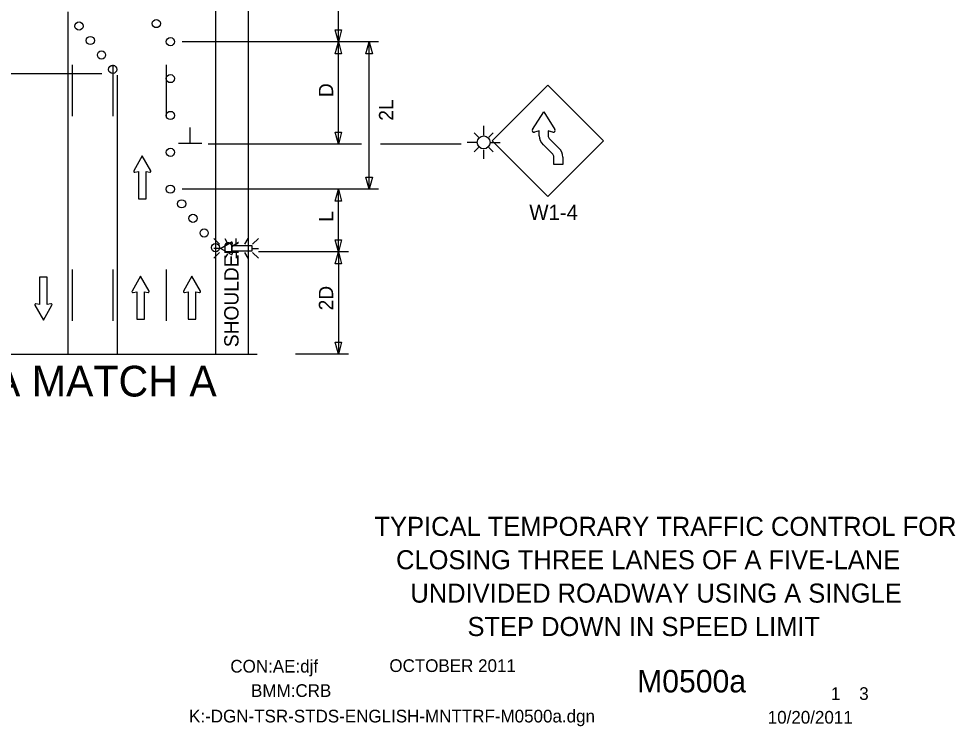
# Model space of a CAD drawing. Extents: x 16738 to 19504, y 5697 to 6916.
# Drawn here: x 16987.4 to 17444.4, y 5931.8 to 6277.3 of the extents above; entities that cross this region are included whole.
import ezdxf

# ---------------------------------------------------------------- set-up
doc = ezdxf.new("R2010")
doc.units = 0
for name, color, linetype in [('ALI_LEGAL_EX', 7, 'Continuous'), ('BORDER', 7, 'Continuous'), ('BORDER_SIGNAL_WO', 7, 'Continuous'), ('MT_SCRATCH_LEVEL_E', 7, 'Continuous'), ('PAVT_EDGE_EX', 7, 'Continuous'), ('TRAFFIC_SIGNS_PR', 7, 'Continuous'), ('TYPICAL_TEXT_DIMEN_PR', 7, 'Continuous')]:
    doc.layers.add(name, color=color, linetype=linetype)

msp = doc.modelspace()

# ---------------------------------------------------------------- linework, layer by layer
at = {"layer": 'ALI_LEGAL_EX'}
for points in [[(17013.43, 6254.77), (17013.43, 6229.77)], [(17033.43, 6254.77), (17033.43, 6229.77)], [(17059.43, 6254.77), (17059.43, 6229.77)], [(17013.43, 6154.77), (17013.43, 6129.77)], [(17033.43, 6154.77), (17033.43, 6129.77)], [(17059.43, 6154.77), (17059.43, 6129.77)]]:
    msp.add_lwpolyline(points, dxfattribs=at)
at = {"layer": 'MT_SCRATCH_LEVEL_E'}
for p, q in [((17047.71, 6210.28), (17043.6, 6203.04)), ((17047.71, 6210.28), (17043.6, 6203.04)), ((17051.85, 6203.04), (17047.71, 6210.28)), ((17051.85, 6203.04), (17047.71, 6210.28)), ((17044.08, 6202.35), (17045.85, 6202.67)), ((17044.08, 6202.35), (17045.85, 6202.67)), ((17045.85, 6202.67), (17045.85, 6189.41)), ((17045.85, 6202.67), (17045.85, 6189.41)), ((17049.6, 6189.41), (17049.6, 6202.67)), ((17049.6, 6202.67), (17051.37, 6202.35)), ((17049.6, 6189.41), (17049.6, 6202.67)), ((17049.6, 6202.67), (17051.37, 6202.35)), ((17045.85, 6189.41), (17049.6, 6189.41)), ((17045.85, 6189.41), (17049.6, 6189.41)), ((17046.87, 6151.51), (17042.76, 6144.27)), ((17046.87, 6151.51), (17042.76, 6144.27)), ((17051.02, 6144.27), (17046.87, 6151.51)), ((17051.02, 6144.27), (17046.87, 6151.51)), ((17071.96, 6151.51), (17067.85, 6144.27)), ((17071.96, 6151.51), (17067.85, 6144.27)), ((17076.11, 6144.27), (17071.96, 6151.51)), ((17076.11, 6144.27), (17071.96, 6151.51)), ((17001.36, 6151.05), (16997.62, 6151.05)), ((16997.62, 6151.05), (16997.62, 6137.79)), ((17001.36, 6151.05), (16997.62, 6151.05)), ((16997.62, 6151.05), (16997.62, 6137.79)), ((17001.36, 6137.79), (17001.36, 6151.05)), ((17001.36, 6137.79), (17001.36, 6151.05)), ((17043.24, 6143.59), (17045.02, 6143.9)), ((17043.24, 6143.59), (17045.02, 6143.9)), ((17045.02, 6143.9), (17045.02, 6130.64)), ((17045.02, 6143.9), (17045.02, 6130.64)), ((17048.76, 6130.64), (17048.76, 6143.9)), ((17048.76, 6143.9), (17050.54, 6143.59)), ((17048.76, 6130.64), (17048.76, 6143.9)), ((17048.76, 6143.9), (17050.54, 6143.59)), ((17068.33, 6143.59), (17070.11, 6143.9)), ((17068.33, 6143.59), (17070.11, 6143.9)), ((17070.11, 6143.9), (17070.11, 6130.64)), ((17070.11, 6143.9), (17070.11, 6130.64)), ((17073.85, 6130.64), (17073.85, 6143.9)), ((17073.85, 6143.9), (17075.63, 6143.59)), ((17073.85, 6130.64), (17073.85, 6143.9)), ((17073.85, 6143.9), (17075.63, 6143.59)), ((16997.62, 6137.79), (16995.84, 6138.11)), ((16997.62, 6137.79), (16995.84, 6138.11)), ((17003.14, 6138.11), (17001.36, 6137.79)), ((17003.14, 6138.11), (17001.36, 6137.79)), ((16995.36, 6137.42), (16999.51, 6130.18)), ((16995.36, 6137.42), (16999.51, 6130.18)), ((16999.51, 6130.18), (17003.62, 6137.42)), ((16999.51, 6130.18), (17003.62, 6137.42)), ((17045.02, 6130.64), (17048.76, 6130.64)), ((17045.02, 6130.64), (17048.76, 6130.64)), ((17070.11, 6130.64), (17073.85, 6130.64)), ((17070.11, 6130.64), (17073.85, 6130.64))]:
    msp.add_line(p, q, dxfattribs=at)
for centre, start, end in [((17044, 6202.81), 150.4248, 279.9638), ((17044, 6202.81), 150.4248, 279.9638), ((17051.44, 6202.81), 260.0362, 29.7731), ((17051.44, 6202.81), 260.0362, 29.7731), ((17043.17, 6144.04), 150.4248, 279.9638), ((17043.17, 6144.04), 150.4248, 279.9638), ((17050.61, 6144.05), 260.0362, 29.7731), ((17050.61, 6144.05), 260.0362, 29.7731), ((17068.26, 6144.04), 150.4248, 279.9638), ((17068.26, 6144.04), 150.4248, 279.9638), ((17075.7, 6144.05), 260.0362, 29.7731), ((17075.7, 6144.05), 260.0362, 29.7731), ((16995.77, 6137.65), 80.0362, 209.7731), ((16995.77, 6137.65), 80.0362, 209.7731), ((17003.21, 6137.65), 330.4248, 99.9638), ((17003.21, 6137.65), 330.4248, 99.9638)]:
    msp.add_arc(centre, 0.463, start, end, dxfattribs=at)
at = {"layer": 'PAVT_EDGE_EX'}
for p, q in [((17083.43, 6911.29), (17083.43, 6113.54)), ((17099.43, 6911.29), (17099.43, 6113.54)), ((17011.43, 6280.66), (17011.43, 6113.54)), ((17035.43, 6249.79), (17035.43, 6113.54))]:
    msp.add_line(p, q, dxfattribs=at)
at = {"layer": 'TRAFFIC_SIGNS_PR'}
for p, q in [((17218.42, 6217.62), (17245.57, 6244.77)), ((17272.73, 6217.62), (17245.57, 6244.77)), ((17214.33, 6220.44), (17214.33, 6224.94)), ((17211.81, 6219.39), (17209.71, 6221.5)), ((17216.84, 6219.39), (17218.95, 6221.5)), ((17211.17, 6216.88), (17206.34, 6216.88)), ((17217.48, 6216.88), (17222.36, 6216.88)), ((17245.57, 6190.47), (17218.42, 6217.62)), ((17247.99, 6211.1), (17243.28, 6215.82)), ((17247.99, 6211.1), (17243.28, 6215.82)), ((17272.73, 6217.62), (17245.57, 6190.47)), ((17251.04, 6214.15), (17246.33, 6218.87)), ((17246.33, 6218.87), (17251.04, 6214.15)), ((17211.81, 6214.37), (17209.71, 6212.26)), ((17214.33, 6208.91), (17214.33, 6213.33)), ((17216.84, 6214.37), (17218.95, 6212.26)), ((17082.56, 6170.02), (17085.38, 6167.2)), ((17088, 6170.02), (17089.21, 6167.93)), ((17093.47, 6167.2), (17093.47, 6170.02)), ((17099.26, 6170.02), (17097.63, 6167.2)), ((17101.55, 6167.2), (17104.38, 6170.02)), ((17085.38, 6165.17), (17082.56, 6165.17)), ((17101.55, 6165.17), (17104.38, 6165.17)), ((17082.56, 6160.32), (17085.38, 6163.14)), ((17089.29, 6162.5), (17088.03, 6160.32)), ((17093.47, 6163.14), (17093.47, 6160.32)), ((17097.6, 6163.14), (17099.23, 6160.32)), ((17101.55, 6163.14), (17104.38, 6160.32))]:
    msp.add_line(p, q, dxfattribs=at)
for points in [[(17238.12, 6223.14), (17243.61, 6231.75), (17249.09, 6223.14)], [(17238.12, 6223.14), (17243.61, 6231.75), (17249.09, 6223.14)], [(17241.45, 6220.13), (17241.45, 6222.49), (17239.09, 6221.85)], [(17241.45, 6220.13), (17241.45, 6222.49), (17239.09, 6221.85)], [(17248.13, 6221.85), (17245.77, 6222.49), (17245.77, 6220.2)], [(17248.13, 6221.84), (17247.29, 6222.07), (17245.77, 6222.49), (17245.77, 6220.2)], [(17252.91, 6209.73), (17252.91, 6206.03), (17248.59, 6206.03), (17248.59, 6209.73)], [(17091.14, 6162.16), (17085.83, 6165.17), (17091.14, 6168.21)], [(17091.64, 6167.85), (17091.41, 6166.56), (17101.14, 6166.56), (17101.14, 6163.81), (17091.41, 6163.81), (17091.64, 6162.51)]]:
    msp.add_lwpolyline(points, dxfattribs=at)
for centre, radius in [((17016.87, 6273.67), 2), ((17054.6, 6274.9), 2), ((17022.35, 6266.62), 2), ((17061.46, 6266.05), 2), ((17061.46, 6266.05), 2), ((17027.84, 6259.56), 2), ((17033.32, 6252.51), 2), ((17061.46, 6248.05), 2), ((17061.46, 6230.05), 2), ((17214.33, 6216.88), 3.15), ((17061.46, 6212.05), 2), ((17061.46, 6194.05), 2), ((17066.95, 6186.92), 2), ((17072.45, 6179.79), 2), ((17077.95, 6172.66), 2), ((17083.45, 6165.54), 2)]:
    msp.add_circle(centre, radius, dxfattribs=at)
for centre, radius, start, end in [((17238.86, 6222.68), 0.866, 147.7292, 285.3172), ((17238.86, 6222.68), 0.866, 147.7196, 285.3201), ((17229.01, 6228.94), 10.8, 327.5335, 327.5431), ((17241.94, 6211.43), 10.8, 105.3192, 105.32), ((17247.62, 6220.19), 6.17, 180.6181, 225.7875), ((17247.62, 6220.2), 6.17, 180.6245, 225.2313), ((17247.62, 6220.2), 1.85, 179.8762, 225.7877), ((17247.62, 6220.19), 1.85, 180, 225.7875), ((17248.36, 6222.68), 0.866, 254.6148, 32.4712), ((17246.74, 6209.73), 1.85, 0, 47.628), ((17246.74, 6209.73), 6.17, 0, 45.7883), ((17091.31, 6167.91), 0.341, 350.0407, 118.5167), ((17091.31, 6162.45), 0.341, 241.1084, 9.2692)]:
    msp.add_arc(centre, radius, start, end, dxfattribs=at)
at = {"layer": 'TYPICAL_TEXT_DIMEN_PR'}
for p, q in [((17143.43, 6266.05), (17143.43, 6329.72)), ((17143.43, 6266.05), (17141.86, 6271.91)), ((17141.86, 6271.91), (17143.43, 6271.91)), ((17143.43, 6271.91), (17145, 6271.91)), ((17145, 6271.91), (17143.43, 6266.05)), ((17163.01, 6266.05), (17067.2, 6266.05)), ((17141.86, 6260.19), (17143.43, 6266.05)), ((17143.43, 6216.05), (17143.43, 6266.05)), ((17143.43, 6266.05), (17145, 6260.19)), ((17156.86, 6260.19), (17158.43, 6266.05)), ((17158.43, 6194.05), (17158.43, 6266.05)), ((17158.43, 6266.05), (17160.01, 6260.19)), ((17143.43, 6260.19), (17141.86, 6260.19)), ((17145, 6260.19), (17143.43, 6260.19)), ((17158.43, 6260.19), (17156.86, 6260.19)), ((17160.01, 6260.19), (17158.43, 6260.19)), ((16898.34, 6250.52), (17027.97, 6250.52)), ((17071.1, 6216.41), (17071.1, 6224.19)), ((17143.43, 6216.05), (17141.86, 6221.91)), ((17141.86, 6221.91), (17143.43, 6221.91)), ((17143.43, 6221.91), (17145.01, 6221.91)), ((17145.01, 6221.91), (17143.43, 6216.05)), ((17076.72, 6216.41), (17065.47, 6216.41)), ((17154.76, 6216.05), (17079.85, 6216.05)), ((17203.37, 6216.05), (17163.93, 6216.05)), ((17158.43, 6194.05), (17156.86, 6199.91)), ((17156.86, 6199.91), (17158.43, 6199.91)), ((17158.43, 6199.91), (17160.01, 6199.91)), ((17160.01, 6199.91), (17158.43, 6194.05)), ((17163.01, 6194.05), (17067.2, 6194.05)), ((17141.86, 6188.19), (17143.43, 6194.05)), ((17143.43, 6163.54), (17143.43, 6194.05)), ((17143.43, 6194.05), (17145, 6188.19)), ((17143.43, 6188.19), (17141.86, 6188.19)), ((17145, 6188.19), (17143.43, 6188.19)), ((17143.43, 6163.54), (17141.86, 6169.4)), ((17141.86, 6169.4), (17143.43, 6169.4)), ((17143.43, 6169.4), (17145, 6169.4)), ((17145, 6169.4), (17143.43, 6163.54)), ((17148.43, 6163.54), (17104.45, 6163.54)), ((17141.86, 6157.68), (17143.43, 6163.54)), ((17143.43, 6163.54), (17145, 6157.68)), ((17143.43, 6163.54), (17143.43, 6113.54)), ((17143.43, 6157.68), (17141.86, 6157.68)), ((17145, 6157.68), (17143.43, 6157.68)), ((17143.43, 6113.54), (17141.86, 6119.4)), ((17141.86, 6119.4), (17143.43, 6119.4)), ((17143.43, 6119.4), (17145, 6119.4)), ((17145, 6119.4), (17143.43, 6113.54)), ((16943.13, 6113.54), (17103.73, 6113.54)), ((17148.43, 6113.54), (17122.43, 6113.54))]:
    msp.add_line(p, q, dxfattribs=at)

# ---------------------------------------------------------------- texts
at = {"layer": 'BORDER'}
for s, p in [('TYPICAL TEMPORARY TRAFFIC CONTROL FOR', (17161.04, 6024.8)), ('CLOSING THREE LANES OF A FIVE-LANE', (17171.56, 6008.5)), ('UNDIVIDED ROADWAY USING A SINGLE', (17178.56, 5992.2)), ('STEP DOWN IN SPEED LIMIT', (17206.42, 5975.9))]:
    msp.add_text(s, height=9.3, dxfattribs=at).set_placement(p)
at = {"layer": 'BORDER_SIGNAL_WO'}
for s, height, p in [('CON:AE:djf', 6.2, (17090.69, 5958.06)), ('    OCTOBER 2011    ', 6.2, (17159.08, 5958.34)), ('    M0500a   ', 11, (17272.86, 5948.38)), ('BMM:CRB   ', 6.2, (17100.81, 5946.17)), (' 1    3 ', 6.2, (17381.45, 5944.7)), ('K:-DGN-TSR-STDS-ENGLISH-MNTTRF-M0500a.dgn        ', 6.2, (17070.55, 5933.71)), ('10/20/2011    ', 6.2, (17352.93, 5933.13))]:
    msp.add_text(s, height=height, dxfattribs=at).set_placement(p)
at = {"layer": 'TRAFFIC_SIGNS_PR'}
msp.add_text('W1-4', height=7.44, dxfattribs=at).set_placement((17236.58, 6179.03))
at = {"layer": 'TYPICAL_TEXT_DIMEN_PR'}
for s, p in [('D', (17140.88, 6238.99)), ('2L', (17170.23, 6227.48)), ('L', (17140.88, 6178.15)), ('SHOULDER', (17094.71, 6116.92)), ('2D', (17140.88, 6134.88))]:
    msp.add_text(s, height=7, rotation=90, dxfattribs=at).set_placement(p)
msp.add_text('A MATCH A', height=15, dxfattribs=at).set_placement((16974.85, 6092.84))

doc.saveas('drawing.dxf')
